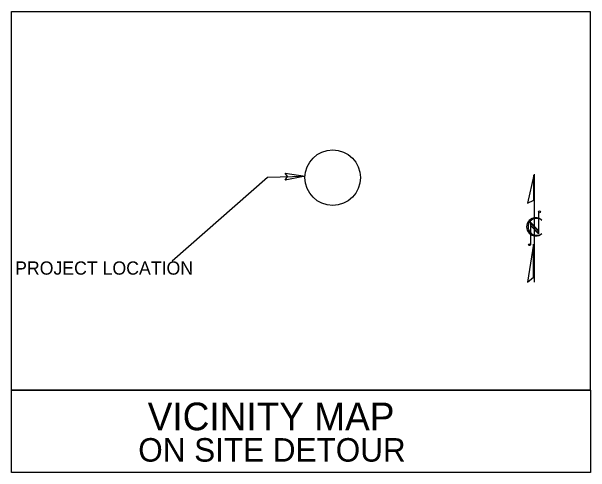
# Model space of a CAD drawing. Extents: x 2241278 to 2254132, y 649924 to 670434.
# Drawn here: x 2246060 to 2248152, y 668768 to 670434 of the extents above; entities that cross this region are included whole.
import ezdxf

# ---------------------------------------------------------------- set-up
doc = ezdxf.new("R2010")
doc.units = 0
for name, color, linetype in [('Prop Terminator CELL', 7, 'Continuous'), ('Sheet Block Title CELL', 7, 'Continuous'), ('Sheet North Arrow CELL', 7, 'Continuous')]:
    doc.layers.add(name, color=color, linetype=linetype)

msp = doc.modelspace()

# ---------------------------------------------------------------- linework, layer by layer
at = {"layer": 'Prop Terminator CELL'}
msp.add_lwpolyline([(2247048.5, 669849.6), (2247120.8, 669838.7), (2247048.7, 669824.4), (2247057.6, 669837.4)], close=True, dxfattribs=at)
at = {"layer": 'Sheet Block Title CELL'}
for p, q in [((2246640.5, 669533.4), (2246985.2, 669835.8)), ((2246985.2, 669835.8), (2247120.8, 669838.7))]:
    msp.add_line(p, q, dxfattribs=at)
for points in [[(2246060.3, 670434.3), (2248151.1, 670434.3), (2248151.1, 669065.9), (2246060.3, 669065.9)], [(2246060.3, 669065.9), (2248151.7, 669065.9), (2248151.7, 668768), (2246060.3, 668768)]]:
    msp.add_lwpolyline(points, close=True, dxfattribs=at)
msp.add_circle((2247220.6, 669833.8), 100.4, dxfattribs=at)
at = {"layer": 'Sheet North Arrow CELL'}
for p, q in [((2247949.8, 669456.1), (2247949.8, 669846.1)), ((2247964.5, 669710.4), (2247964.5, 669630.4)), ((2247964.5, 669642.8), (2247934.7, 669672.7)), ((2247934.7, 669672.7), (2247934.7, 669591.3)), ((2247964.5, 669639.9), (2247934.7, 669669.7)), ((2247934.7, 669669.7), (2247934.7, 669662.4)), ((2247975.5, 669680.6), (2247976, 669680.3)), ((2247964.5, 669632.6), (2247934.7, 669662.4)), ((2247934.7, 669662.4), (2247964.5, 669632.6)), ((2247964.5, 669630.4), (2247934.7, 669660.2)), ((2247964.5, 669632.6), (2247964.5, 669639.9))]:
    msp.add_line(p, q, dxfattribs=at)
for points in [[(2247947.1, 669842.7), (2247924.8, 669741.4), (2247947.1, 669752.7)], [(2247946.6, 669593.5), (2247924.5, 669456.1), (2247946.6, 669473.5)]]:
    msp.add_lwpolyline(points, close=True, dxfattribs=at)
for centre in [(2247967.7, 669710.3), (2247931.5, 669591.2)]:
    msp.add_circle(centre, 3.18, dxfattribs=at)
for centre, radius, start, end in [((2247953.9, 669656), 32.8, 47.84, 312.3941), ((2247957.1, 669656), 30.7, 53.095, 308.6287)]:
    msp.add_arc(centre, radius, start, end, dxfattribs=at)

# ---------------------------------------------------------------- texts
at = {"layer": 'Sheet Block Title CELL'}
for s, height, p in [('PROJECT LOCATION', 47.812, (2246073, 669483)), ('VICINITY MAP', 100, (2246552.1, 668920.4)), ('ON SITE DETOUR', 85, (2246517.9, 668807))]:
    msp.add_text(s, height=height, dxfattribs=at).set_placement(p)

doc.saveas('drawing.dxf')
